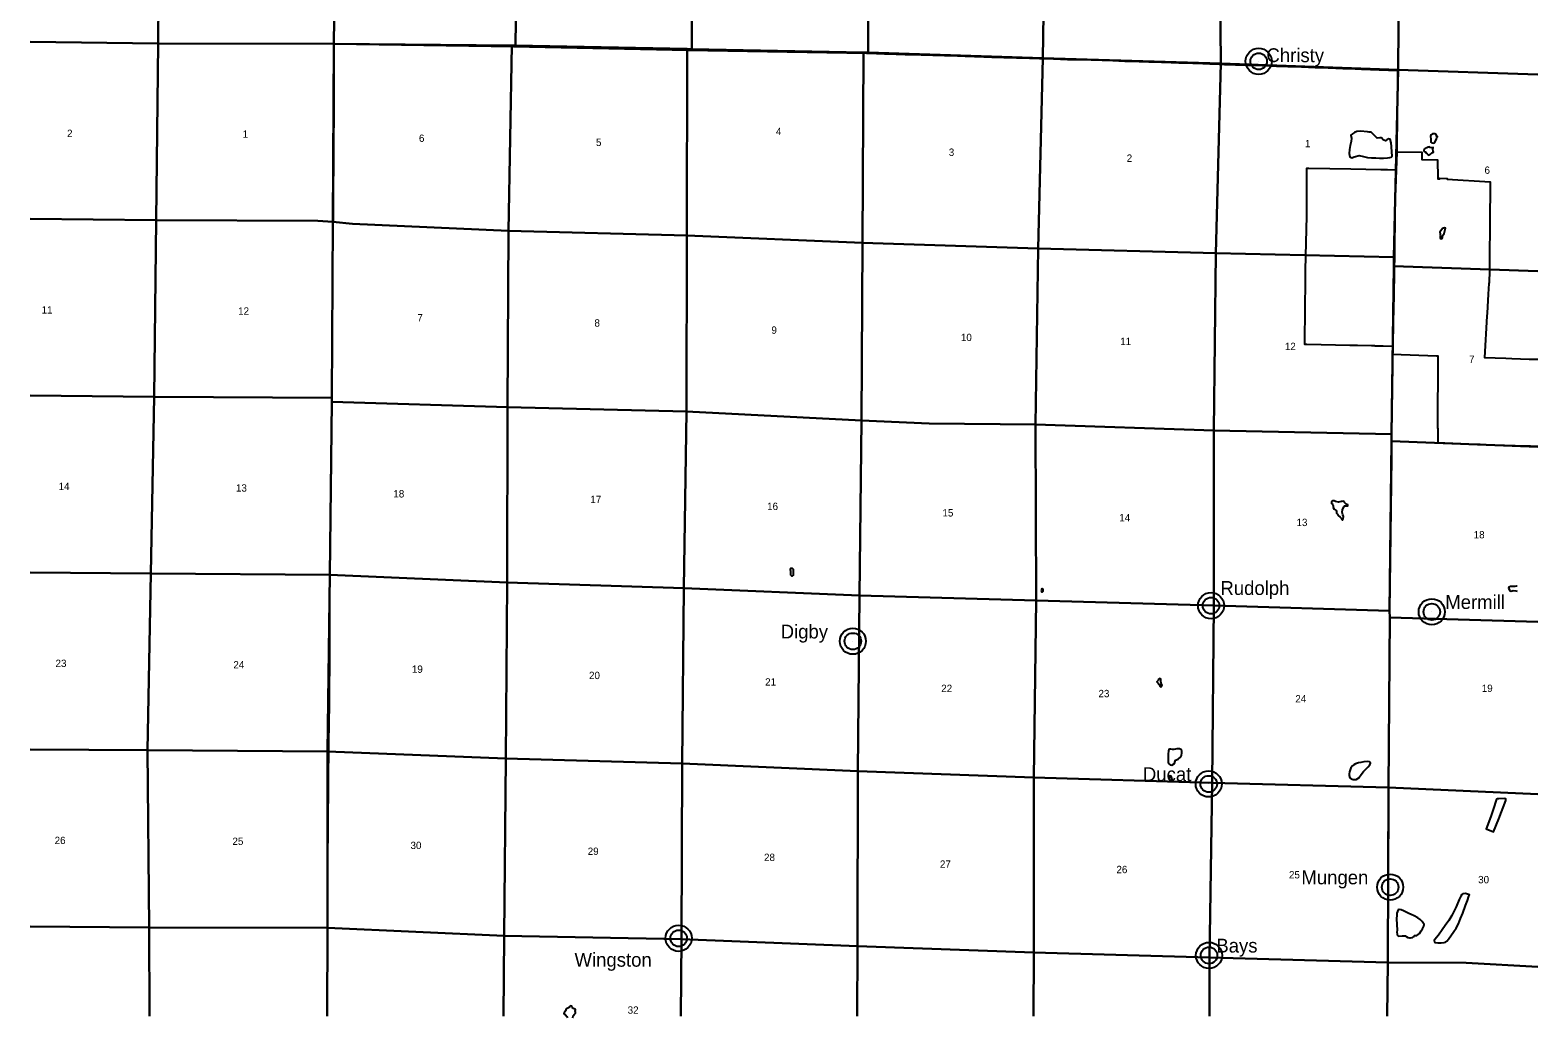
# Model space of a CAD drawing. Extents: x 0 to 680, y 0 to 834.
# Drawn here: x 44.7 to 374.7, y 503.7 to 720 of the extents above; entities that cross this region are included whole.
import ezdxf

# ---------------------------------------------------------------- set-up
doc = ezdxf.new("R2010")
doc.units = 0
for name, color, linetype in [('GM_X_Corporation', 7, 'Continuous'), ('GM_X_Minor_Lake', 7, 'Continuous'), ('GM_X_Section', 7, 'Continuous'), ('GM_X_Section_Text', 7, 'Continuous'), ('GM_X_Township', 7, 'Continuous'), ('GM_X_Unincorporated', 7, 'Continuous'), ('GM_X_Unincorporated_Location', 7, 'Continuous'), ('GM_X_Unincorporated_Text', 7, 'Continuous')]:
    doc.layers.add(name, color=color, linetype=linetype)

msp = doc.modelspace()

# ---------------------------------------------------------------- linework, layer by layer
at = {"layer": 'GM_X_Corporation'}
msp.add_lwpolyline([(374.69, 628.81), (373.07, 628.87), (372.49, 628.89), (372.16, 628.9), (367.41, 629.07), (362.57, 629.2), (362.04, 629.22), (360.12, 629.27), (358.67, 629.33), (357.86, 629.37), (357.65, 629.38), (356.07, 629.45), (355.68, 629.47), (354.35, 629.52), (354.02, 629.54), (353.96, 629.54), (353.58, 629.55), (352.86, 629.58), (352.91, 632.77), (352.78, 632.78), (352.9, 648.58), (352.48, 648.6), (342.89, 648.93), (342.9, 649.07), (342.93, 650.75), (340.85, 650.8), (339.94, 650.81), (339.82, 650.81), (339.48, 650.82), (339.26, 650.82), (339.11, 650.82), (338.95, 650.83), (338.31, 650.84), (335.2, 650.9), (333.52, 650.94), (324.13, 651.12), (323.69, 651.12), (323.72, 653.92), (323.75, 656.72), (323.79, 660.11), (323.86, 663.95), (323.86, 664.87), (323.86, 667.32), (323.92, 670.53), (324.1, 679.31), (324.1, 680.15), (324.14, 689.79), (324.4, 689.78), (324.58, 689.77), (333.75, 689.61), (340.34, 689.49), (341.8, 689.46), (343.71, 689.42), (343.75, 690.4), (343.75, 690.5), (343.77, 690.99), (343.77, 691.28), (343.79, 693.35), (349.33, 693.25), (349.29, 691.69), (352.71, 691.61), (352.82, 687.61), (352.82, 687.45), (353.26, 687.44), (353.27, 687.58), (354.82, 687.52), (354.82, 687.37), (364.27, 686.8), (364.19, 677.35), (364.12, 670.32), (364.12, 670.28), (364.13, 669.96), (364.14, 669.83), (364.14, 669.62), (364.11, 667.48), (364.1, 667.14), (364.02, 664.9), (364.01, 664.7), (364, 664.51), (363.85, 662.2), (363.6, 658.03), (363.56, 657.36), (363.03, 648.27), (367.71, 648.13), (369.02, 648.09), (372.81, 647.97), (374.69, 647.91)], dxfattribs=at)
at = {"layer": 'GM_X_Minor_Lake'}
for p, q in [((337.39, 697.71), (335.85, 697.85)), ((351.23, 696.62), (351.27, 696.16)), ((350.41, 694.25), (350, 694.07)), ((353.31, 675.16), (353.35, 674.98)), ((331.76, 616.75), (331.62, 616.75)), ((211.08, 601.53), (211.12, 601.27)), ((266.04, 597.42), (265.98, 597.3)), ((370.05, 598.21), (369.62, 598.19)), ((370.2, 598.23), (370.05, 598.21)), ((291.6, 577.6), (291.43, 577.44)), ((295.65, 562.61), (295.4, 562.51)), ((334.42, 559.13), (334.09, 558.91)), ((293.99, 556.33), (294.03, 556.15)), ((364.99, 549.54), (364.39, 547.83)), ((356.82, 528.04), (355.89, 526.15)), ((343.76, 525.38), (343.92, 522.89)), ((161.94, 505.48), (161.86, 505.22))]:
    msp.add_line(p, q, dxfattribs=at)
for points in [[(335.85, 697.85), (335.09, 697.79), (334.55, 697.59), (334.13, 697.29), (333.79, 696.98), (333.89, 696.32), (333.85, 695.58), (333.65, 694.73), (333.49, 693.87), (333.36, 692.96), (333.57, 692.21), (334, 692.06), (334.52, 692.25), (335.6, 692.51), (336.52, 692.29), (337.4, 692.11), (338.26, 692.02), (339.2, 692), (340.01, 691.97), (340.94, 691.96), (341.79, 692.03), (342.29, 692.07), (342.58, 692.17), (342.8, 692.49), (342.74, 693.25), (342.66, 694.49), (342.56, 695.31), (342.39, 696.08), (342.11, 696.2), (341.7, 696.02), (341.32, 695.76), (340.86, 695.98), (340.49, 696.39), (340.11, 696.42), (339.49, 696.34), (339.07, 696.76), (338.53, 697.32), (338.22, 697.61), (337.77, 697.68), (337.39, 697.71)], [(351.27, 696.16), (351.27, 695.95), (351.27, 695.69), (351.29, 695.44), (351.49, 695.29), (351.77, 695.26), (352.1, 695.34), (352.36, 695.8), (352.51, 696.17), (352.6, 696.46), (352.73, 696.6), (352.73, 696.68), (352.59, 696.72), (352.43, 697.12), (352.12, 697.29), (351.61, 697.26), (351.31, 697.06), (351.23, 696.84), (351.23, 696.62)], [(350, 694.07), (349.82, 693.94), (349.76, 693.64), (349.88, 693.43), (350.13, 693.34), (350.2, 693.11), (350.45, 692.88), (350.67, 692.7), (350.93, 692.6), (351.2, 692.84), (351.47, 693.11), (351.82, 693.28), (351.76, 693.5), (351.69, 693.92), (351.81, 694.26), (351.47, 694.2), (351.06, 694.27), (350.95, 694.42), (350.67, 694.36), (350.41, 694.25)], [(353.35, 674.98), (353.33, 674.72), (353.32, 674.5), (353.46, 674.28), (353.67, 674.34), (353.79, 674.56), (353.79, 674.97), (354.17, 675.46), (354.51, 676.6), (354.24, 676.7), (353.86, 676.57), (353.67, 676.34), (353.4, 675.98), (353.24, 675.77), (353.31, 675.49), (353.31, 675.16)], [(331.62, 616.75), (331.37, 616.67), (331.05, 616.62), (330.41, 616.74), (330.09, 616.89), (329.78, 616.89), (329.52, 616.63), (329.52, 616.36), (329.79, 616.09), (329.88, 615.75), (329.91, 615.43), (330.1, 615.06), (330.53, 614.82), (330.62, 614.55), (330.59, 614.23), (330.85, 614), (331.02, 613.69), (331.4, 613.35), (331.66, 613.15), (331.76, 612.86), (331.94, 612.7), (332.07, 612.97), (332.17, 613.48), (331.99, 613.83), (331.83, 614.43), (331.95, 614.93), (332.2, 615.61), (332.39, 615.86), (332.73, 615.79), (333.1, 615.8), (333.1, 616.06), (332.74, 616.22), (332.39, 616.58), (332.13, 616.84), (331.76, 616.75)], [(211.12, 601.27), (211.15, 601.01), (211.14, 600.75), (211.3, 600.53), (211.54, 600.48), (211.75, 600.64), (211.78, 601.04), (211.78, 601.49), (211.78, 601.85), (211.56, 602.09), (211.13, 602.13), (211.02, 601.85), (211.08, 601.53)], [(265.98, 597.3), (266.08, 597.02), (266.28, 596.98), (266.45, 597.17), (266.39, 597.42), (266.29, 597.62), (266.2, 597.65), (266.05, 597.58), (266.04, 597.42)], [(369.62, 598.19), (369.14, 598.15), (368.73, 598.15), (368.34, 598.02), (368.3, 597.82), (368.46, 597.42), (368.62, 597.22), (368.83, 597.14), (369.29, 597.25), (369.9, 597.21), (370.2, 597.17)], [(291.43, 577.44), (291.3, 577.28), (291.46, 577.14), (291.57, 577.05), (291.65, 576.8), (291.85, 576.73), (291.95, 576.61), (291.96, 576.35), (292.08, 576.2), (292.3, 576.26), (292.43, 576.58), (292.27, 576.97), (292.16, 577.5), (292.17, 577.86), (291.9, 578), (291.69, 577.85), (291.6, 577.6)], [(295.4, 562.51), (295.01, 562.47), (294.73, 562.47), (294.37, 562.53), (294.17, 562.54), (293.96, 562.5), (293.82, 562.1), (293.78, 561.49), (293.75, 561.02), (293.78, 560.59), (293.75, 560.19), (293.75, 559.8), (293.84, 559.42), (294.18, 559.1), (294.56, 559.05), (295.18, 559.37), (295.32, 559.91), (295.38, 560.14), (295.95, 560.39), (296.55, 560.84), (296.71, 561.19), (296.79, 561.72), (296.77, 562.14), (296.67, 562.42), (296.26, 562.61), (295.99, 562.65), (295.65, 562.61)], [(334.09, 558.91), (333.78, 558.44), (333.62, 558.05), (333.46, 557.61), (333.41, 557.12), (333.41, 556.78), (333.53, 556.28), (333.8, 556.05), (334.3, 555.89), (334.91, 555.89), (335.54, 556.25), (335.99, 557.01), (336.53, 557.68), (337.01, 558.16), (337.57, 558.65), (337.91, 559.09), (338.07, 559.51), (337.88, 559.76), (337.43, 559.82), (336.63, 559.78), (335.94, 559.66), (335.42, 559.53), (334.75, 559.31), (334.42, 559.13)], [(294.03, 556.15), (294.1, 555.92), (294.23, 555.77), (294.51, 555.79), (294.69, 555.92), (294.58, 556.19), (294.48, 556.44), (294.34, 556.6), (294.18, 556.69), (294.06, 556.66), (293.99, 556.41), (293.99, 556.33)], [(364.39, 547.83), (363.4, 545.11), (364.98, 544.46), (366.12, 547.29), (367.65, 551.33), (367.71, 551.55), (367.68, 551.66), (367.4, 551.71), (366.15, 551.7), (365.87, 551.7), (365.71, 551.58), (365.59, 551.39), (364.99, 549.54)], [(355.89, 526.15), (355.24, 525.06), (354.42, 523.9), (353.77, 522.95), (352.92, 521.83), (352.16, 520.87), (352, 520.62), (352.04, 520.39), (352.18, 520.24), (352.8, 520.14), (353.51, 520.13), (354.18, 520.19), (354.46, 520.31), (354.76, 520.5), (355.11, 520.92), (356.33, 522.59), (356.78, 523.33), (357.34, 524.31), (357.79, 525.48), (358.26, 526.6), (358.87, 528.29), (359.31, 529.4), (359.62, 530.36), (359.7, 530.63), (358.83, 530.97), (358.31, 530.9), (358.07, 530.71), (357.84, 530.36), (357.49, 529.62), (356.82, 528.04)], [(343.92, 522.89), (343.86, 522.45), (343.88, 522.01), (343.97, 521.75), (344.22, 521.63), (344.96, 521.68), (345.65, 521.66), (345.89, 521.5), (346.26, 521.31), (346.58, 521.25), (346.85, 521.2), (347.26, 521.32), (347.45, 521.48), (347.72, 521.73), (348.17, 521.75), (348.77, 522.15), (349.19, 522.73), (349.48, 523.22), (349.75, 523.75), (349.79, 524.17), (349.37, 524.84), (348.92, 525.25), (348.4, 525.59), (347.61, 526.02), (346.99, 526.37), (346.48, 526.59), (345.88, 526.87), (345.26, 527.12), (344.79, 527.34), (344.35, 527.45), (344.1, 527.35), (343.96, 527.03), (343.84, 526.6), (343.81, 526.2), (343.76, 525.38)], [(161.86, 505.22), (161.6, 504.84), (161.54, 504.62), (161.69, 504.46), (161.87, 504.36), (162.17, 503.99), (162.34, 503.71)], [(163.44, 503.71), (163.46, 503.73), (163.54, 504.18), (163.87, 504.49), (164.09, 504.7), (164.05, 505.01), (163.98, 505.2), (164.05, 505.57), (163.64, 505.74), (163.32, 505.95), (163.25, 506.24), (162.99, 506.33), (162.73, 506.2), (162.64, 505.98), (162.36, 505.85), (162.1, 505.72), (161.94, 505.48)]]:
    msp.add_lwpolyline(points, dxfattribs=at)
at = {"layer": 'GM_X_Section'}
for points in [[(44.69, 756.13), (73.02, 755.95), (72.69, 717.09), (44.69, 717.41)], [(374.69, 710.26), (344.09, 711.3), (344.39, 749.46), (374.69, 748.56)], [(44.69, 717.41), (72.69, 717.09), (72.3, 678.37), (44.69, 678.67)], [(374.69, 667.23), (343.18, 668.34), (343.19, 670.27), (344.09, 711.3), (374.69, 710.26)], [(44.69, 678.67), (72.3, 678.37), (71.83, 639.66), (44.69, 639.98)], [(374.69, 628.74), (342.67, 629.97), (342.65, 631.52), (343.18, 668.34), (374.69, 667.23)], [(44.69, 639.98), (71.83, 639.66), (71.08, 601.04), (44.69, 601.24)], [(374.69, 590.44), (342.26, 591.38), (342.24, 592.8), (342.67, 629.97), (374.69, 628.74)], [(44.69, 601.24), (71.08, 601.04), (70.39, 562.33), (44.69, 562.46)], [(374.69, 552.66), (341.97, 554.17), (342.26, 591.38), (374.69, 590.44)], [(44.69, 562.46), (70.39, 562.33), (70.74, 523.53), (44.69, 523.7)], [(374.69, 514.87), (359.03, 515.75), (341.89, 515.83), (341.97, 554.17), (374.69, 552.66)], [(44.69, 523.7), (70.74, 523.53), (70.78, 504.07)], [(70.78, 504.07), (70.74, 523.53), (109.8, 523.42), (109.73, 504.07)], [(109.73, 504.07), (109.8, 523.42), (148.46, 521.67), (148.32, 504.07)], [(148.32, 504.07), (148.46, 521.67), (187.24, 520.95), (187.09, 504.07)], [(187.09, 504.07), (187.24, 520.95), (225.76, 519.39), (225.72, 504.07)], [(225.72, 504.07), (225.76, 519.39), (264.36, 518.01), (264.3, 504.07)], [(264.3, 504.07), (264.36, 518.01), (302.85, 516.94), (302.85, 504.07)], [(302.85, 504.07), (302.85, 516.94), (341.89, 515.83), (341.72, 504.07)], [(341.72, 504.07), (341.89, 515.83), (359.03, 515.75), (374.69, 514.87)]]:
    msp.add_lwpolyline(points, dxfattribs=at)
for points in [[(73.02, 755.95), (111.68, 755.71), (111.16, 716.99), (72.69, 717.09)], [(111.68, 755.71), (151.41, 755.16), (150.89, 716.62), (150.15, 716.6), (111.16, 716.99)], [(151.41, 755.16), (189.5, 754.4), (189.54, 715.85), (188.47, 715.88), (150.89, 716.62)], [(228.16, 753.52), (228.14, 715.12), (227.12, 715.11), (189.54, 715.85), (189.5, 754.4)], [(266.9, 752.37), (266.32, 713.83), (228.14, 715.12), (228.16, 753.52)], [(266.9, 752.37), (304.96, 751.22), (305.27, 712.65), (266.32, 713.83)], [(304.96, 751.22), (344.34, 750), (344.39, 749.46), (344.09, 711.3), (305.27, 712.65)], [(111.16, 716.99), (110.94, 678), (107.67, 678.25), (72.3, 678.37), (72.69, 717.09)], [(149.4, 676.04), (115.26, 677.54), (110.94, 678), (111.16, 716.99), (150.15, 716.6)], [(188.47, 715.88), (188.39, 675.05), (149.4, 676.04), (150.15, 716.6), (150.89, 716.62)], [(188.47, 715.88), (189.54, 715.85), (227.12, 715.11), (226.87, 673.4), (188.39, 675.05)], [(227.12, 715.11), (228.14, 715.12), (266.32, 713.83), (265.31, 672.18), (226.87, 673.4)], [(266.32, 713.83), (305.27, 712.65), (304.23, 671.13), (265.31, 672.18)], [(305.27, 712.65), (344.09, 711.3), (343.19, 670.27), (304.23, 671.13)], [(72.3, 678.37), (107.67, 678.25), (110.94, 678), (110.69, 639.47), (71.83, 639.66)], [(110.94, 678), (115.26, 677.54), (149.4, 676.04), (149.16, 637.44), (110.71, 638.6), (110.69, 639.47)], [(149.4, 676.04), (188.39, 675.05), (188.33, 636.45), (149.16, 637.44)], [(188.39, 675.05), (226.87, 673.4), (226.62, 634.51), (188.33, 636.45)], [(226.87, 673.4), (265.31, 672.18), (264.74, 633.6), (241.47, 633.86), (226.62, 634.51)], [(265.31, 672.18), (304.23, 671.13), (303.8, 632.32), (264.74, 633.6)], [(304.23, 671.13), (343.19, 670.27), (343.18, 668.34), (342.65, 631.52), (303.8, 632.32)], [(110.69, 639.47), (110.71, 638.6), (110.26, 600.7), (71.08, 601.04), (71.83, 639.66)], [(110.71, 638.6), (149.16, 637.44), (149.08, 599.04), (110.26, 600.7)], [(149.16, 637.44), (188.33, 636.45), (187.75, 597.77), (149.08, 599.04)], [(188.33, 636.45), (226.62, 634.51), (226.23, 596.19), (187.75, 597.77)], [(226.62, 634.51), (241.47, 633.86), (264.74, 633.6), (264.92, 595.1), (226.23, 596.19)], [(264.74, 633.6), (303.8, 632.32), (303.8, 594), (264.92, 595.1)], [(303.8, 632.32), (342.65, 631.52), (342.67, 629.97), (342.24, 592.8), (303.8, 594)], [(71.08, 601.04), (110.26, 600.7), (109.78, 562.06), (70.39, 562.33)], [(110.26, 600.7), (149.08, 599.04), (148.82, 560.47), (109.78, 562.06)], [(149.08, 599.04), (187.75, 597.77), (187.44, 559.42), (148.82, 560.47)], [(187.75, 597.77), (226.23, 596.19), (225.82, 557.71), (187.44, 559.42)], [(226.23, 596.19), (264.92, 595.1), (264.36, 556.34), (225.82, 557.71)], [(264.92, 595.1), (303.8, 594), (303.38, 555.2), (264.36, 556.34)], [(303.8, 594), (342.24, 592.8), (342.26, 591.38), (341.97, 554.17), (303.38, 555.2)], [(109.78, 562.06), (109.8, 523.42), (70.74, 523.53), (70.39, 562.33)], [(148.82, 560.47), (148.46, 521.67), (109.8, 523.42), (109.78, 562.06)], [(148.82, 560.47), (187.44, 559.42), (187.24, 520.95), (148.46, 521.67)], [(187.44, 559.42), (225.82, 557.71), (225.76, 519.39), (187.24, 520.95)], [(225.82, 557.71), (264.36, 556.34), (264.36, 518.01), (225.76, 519.39)], [(264.36, 556.34), (303.38, 555.2), (302.85, 516.94), (264.36, 518.01)], [(303.38, 555.2), (341.97, 554.17), (341.89, 515.83), (302.85, 516.94)]]:
    msp.add_lwpolyline(points, close=True, dxfattribs=at)
at = {"layer": 'GM_X_Township'}
msp.add_lwpolyline([(109.7, 504.07), (109.7, 505.4), (109.72, 506.95), (109.73, 508.26), (109.74, 510.41), (109.76, 513.64), (109.76, 516.5), (109.78, 519.72), (109.81, 523.31), (109.81, 523.43), (109.78, 524.86), (109.77, 526.65), (109.79, 528.8), (109.8, 530.71), (109.83, 533.57), (109.84, 536.55), (109.86, 539.54), (109.9, 544.31), (109.92, 547.18), (109.95, 549.45), (109.96, 551.71), (109.97, 554.46), (110.01, 558.28), (110.04, 560.55), (110.08, 562.23), (110.08, 562.34), (110.08, 562.8), (110.08, 563.4), (110.14, 568.65), (110.18, 571.88), (110.19, 573.31), (110.21, 576.77), (110.25, 580.23), (110.25, 581.66), (110.25, 583.69), (110.26, 586.44), (110.26, 588.47), (110.27, 590.97), (110.27, 593.12), (110.29, 594.44), (110.28, 596.59), (110.28, 598.38), (110.28, 600.29), (110.27, 600.67), (110.25, 601), (110.28, 602.17), (110.35, 605.16), (110.37, 607.43), (110.39, 608.62), (110.44, 611.72), (110.53, 615.9), (110.56, 617.93), (110.61, 620.67), (110.61, 622.11), (110.63, 623.3), (110.65, 624.49), (110.68, 628.31), (110.71, 630.34), (110.71, 631.06), (110.75, 635.59), (110.75, 637.03), (110.74, 638.58), (110.74, 638.74), (110.75, 639.29), (110.76, 639.54), (110.77, 640.49), (110.8, 645.5), (110.84, 652.66), (110.86, 654.81), (110.87, 656.48), (110.88, 659.47), (110.89, 662.21), (110.94, 665.08), (110.95, 666.27), (110.97, 670.57), (110.97, 672.84), (110.98, 674.75), (110.99, 677.13), (111.01, 677.73), (111.03, 677.85), (111.06, 678.01), (111.1, 678.2), (111.11, 678.32), (111.1, 678.78), (111.1, 680.1), (111.09, 681.05), (111.11, 685.95), (111.13, 690.01), (111.14, 691.56), (111.15, 694.06), (111.19, 697.41), (111.21, 699.67), (111.22, 701.23), (111.22, 702.42), (111.23, 703.73), (111.23, 706), (111.23, 707.79), (111.24, 710.3), (111.24, 712.45), (111.23, 713.76), (111.23, 715.07), (111.23, 716.03), (111.24, 716.97), (150.5, 716.41), (188.73, 715.62), (227.76, 714.95), (228.12, 714.94), (231.7, 714.81), (234.21, 714.73), (236.24, 714.67), (239.7, 714.58), (244.83, 714.43), (247.69, 714.34), (249.36, 714.29), (253.42, 714.16), (255.21, 714.1), (257.82, 714.01), (260.56, 713.93), (263.43, 713.86), (265.58, 713.8), (266.5, 713.77), (266.89, 713.76), (268.68, 713.69), (271.78, 713.59), (274.28, 713.53), (276.91, 713.45), (281.68, 713.31), (284.31, 713.22), (287.41, 713.12), (289.55, 713.05), (292.3, 712.96), (294.44, 712.89), (296.11, 712.83), (299.21, 712.73), (301.36, 712.66), (302.91, 712.61), (304.94, 712.53), (305.19, 712.52), (306.13, 712.49), (308.52, 712.41), (310.78, 712.35), (312.93, 712.29), (314.36, 712.23), (317.46, 712.13), (319.96, 712.03), (322.95, 711.92), (324.49, 711.86), (325.92, 711.82), (328.78, 711.72), (330.45, 711.66), (332, 711.61), (333.31, 711.56), (336.06, 711.44), (339.99, 711.28), (342.02, 711.21), (343.8, 711.13), (344, 711.12), (343.8, 693.29), (343.77, 691.29), (343.52, 685.33), (343.45, 683.42), (343.44, 683.15), (343.43, 682.69), (343.43, 681.98), (343.42, 681.38), (343.41, 680.43), (343.4, 679.99), (343.4, 679.41), (343.39, 678.52), (343.38, 678.11), (343.38, 677.92), (343.37, 676.61), (343.36, 676.13), (343.35, 675.18), (343.32, 672.96), (343.31, 671.83), (343.3, 670.76), (343.29, 670.12), (343.26, 668), (343.25, 667.23), (343.25, 666.92), (343.24, 666.17), (343.21, 664.75), (343.2, 664.15), (343.19, 663.58), (343.17, 662.15), (343.07, 658.68), (343.01, 656.44), (342.99, 655.2), (342.95, 651.72), (342.68, 631.52), (342.68, 629.86), (342.64, 626.31), (342.23, 592.85), (342.07, 568.63), (342.07, 568.38), (341.99, 554.22), (341.91, 531.42), (341.79, 515.74), (341.68, 504.07)], dxfattribs=at)
at = {"layer": 'GM_X_Unincorporated'}
for centre, radius in [((313.59, 713.16), 2.86), ((313.59, 713.16), 1.81), ((303.17, 593.97), 2.86), ((303.17, 593.97), 1.81), ((351.48, 592.62), 2.86), ((351.48, 592.62), 1.81), ((224.76, 586.17), 2.86), ((224.76, 586.17), 1.81), ((302.66, 554.93), 2.86), ((302.66, 554.93), 1.81), ((342.37, 532.33), 2.86), ((342.37, 532.33), 1.81), ((186.63, 521.13), 2.86), ((186.63, 521.13), 1.81), ((302.73, 517.38), 2.86), ((302.73, 517.38), 1.81)]:
    msp.add_circle(centre, radius, dxfattribs=at)
at = {"layer": 'GM_X_Unincorporated_Location'}
for p, q in [((313.59, 713.16), (313.59, 713.16)), ((303.17, 593.97), (303.17, 593.97)), ((351.48, 592.62), (351.48, 592.62)), ((224.76, 586.17), (224.76, 586.17)), ((302.66, 554.93), (302.66, 554.93)), ((342.37, 532.33), (342.37, 532.33)), ((186.63, 521.13), (186.63, 521.13)), ((302.73, 517.38), (302.73, 517.38))]:
    msp.add_line(p, q, dxfattribs=at)

# ---------------------------------------------------------------- texts
at = {"layer": 'GM_X_Section_Text'}
for s, height, p in [('2', 1.61, (52.77, 696.59)), ('1', 1.61, (91.2, 696.41)), ('6', 1.61, (129.79, 695.52)), ('4', 1.61, (207.92, 697)), ('5', 1.61, (168.54, 694.61)), ('3', 1.61, (245.76, 692.45)), ('1', 1.61, (323.71, 694.35)), ('2', 1.61, (284.7, 691.15)), ('6', 1.61, (363.02, 688.53)), ('11', 1.607, (47.2, 657.92)), ('12', 1.607, (90.22, 657.67)), ('7', 1.61, (129.44, 656.21)), ('8', 1.61, (168.2, 655.07)), ('9', 1.61, (206.94, 653.5)), ('10', 1.607, (248.41, 651.9)), ('11', 1.607, (283.28, 651.04)), ('12', 1.607, (319.32, 649.93)), ('7', 1.61, (359.63, 647.12)), ('14', 1.607, (50.91, 619.27)), ('13', 1.607, (89.74, 618.94)), ('18', 1.607, (124.19, 617.66)), ('17', 1.607, (167.31, 616.43)), ('16', 1.607, (206, 614.91)), ('15', 1.607, (244.38, 613.49)), ('14', 1.607, (283.08, 612.43)), ('13', 1.607, (321.87, 611.39)), ('18', 1.607, (360.65, 608.7)), ('23', 1.607, (50.25, 580.54)), ('24', 1.607, (89.17, 580.23)), ('19', 1.607, (128.24, 579.26)), ('20', 1.607, (167.02, 577.89)), ('21', 1.607, (205.56, 576.46)), ('22', 1.607, (244.11, 575.05)), ('23', 1.607, (278.52, 573.92)), ('24', 1.607, (321.61, 572.78)), ('19', 1.607, (362.42, 575.07)), ('26', 1.607, (50.05, 541.76)), ('25', 1.607, (88.97, 541.57)), ('30', 1.607, (127.95, 540.67)), ('29', 1.607, (166.73, 539.39)), ('28', 1.607, (205.32, 538.05)), ('27', 1.607, (243.82, 536.57)), ('26', 1.607, (282.46, 535.39)), ('25', 1.607, (320.22, 534.24)), ('30', 1.607, (361.63, 533.18)), ('32', 1.607, (175.47, 504.61))]:
    msp.add_text(s, height=height, rotation=0, dxfattribs=at).set_placement(p)
at = {"layer": 'GM_X_Unincorporated_Text'}
for s, p in [('Christy', (315.29, 712.98)), ('Rudolph', (305.21, 596.31)), ('Mermill', (354.43, 593.24)), ('Digby', (208.96, 586.78)), ('Ducat', (288.25, 555.55)), ('Mungen', (322.94, 532.95)), ('Wingston', (163.84, 514.91)), ('Bays', (304.32, 518.01))]:
    msp.add_text(s, height=3.033, rotation=0, dxfattribs=at).set_placement(p)

doc.saveas('drawing.dxf')
